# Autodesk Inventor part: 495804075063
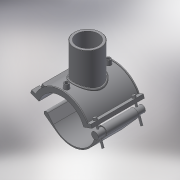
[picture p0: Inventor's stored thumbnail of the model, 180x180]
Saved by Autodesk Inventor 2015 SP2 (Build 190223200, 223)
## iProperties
Created: 2017-07
Part Number: 495804075063
Material: Generic
Description: PLASSON BRANCH SADDLE 75-63
Document SubType Name: Modeling
Designer: KIM
Density: 1 g/cm^3
Appearance: Default
Author: KIM
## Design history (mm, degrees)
derived "495804.ipt"
feature "Solid1::495804.ipt"
feature "Solid2::495804.ipt"
tag "TaggingFeature1"
body "Solid1"
body "Solid2"
other parameters: "d0" = 75, "d2" = 117, "d3" = 18.75, "d4" = 118, "d5" = 0, "d6" = 0.1, "d8" = 0, "d19" = 6, "d20" = 6, "d21" = 70.8, "d23" = 0, "d24" = 35.4, "d26" = 0, "d27" = 3, "d28" = 3, "d29" = 3, "d30" = 25, "d31" = 6, "d32" = 0, "d33" = 0, "d34" = 0.6, "d40" = 48.36, "d41" = 69.3, "d43" = 0, "d45" = 0, "d47" = 140.5, "d48" = 63, "d50" = 0, "d70" = 15, "d72" = 0, "d73" = 6, "d75" = 5, "d76" = 0, "d77" = 3.75, "d78" = 67.5, "d79" = 15, "d80" = 47.2, "d82" = 5 deg, "d84" = 4, "d85" = 14, "d86" = 0, "d87" = 3, "d88" = 0, "d89" = 1, "d90" = 1, "d91" = 94.4, "d92" = 0, "d93" = 0.5, "d94" = 39.47368, "d96" = 94.86, "d97" = 2.36, "d98" = 0, "d102" = 1.89, "d103" = 50.4, "d105" = 0, "d109" = -31.33333, "d117" = 0.63, "d120" = 140 deg, "d121" = 24.228, "d122" = 20 deg, "d123" = 186, "d124" = 55.8, "d126" = 0, "d143" = 78.75, "d150" = 13.5, "d159" = 3.6, "d161" = 1.875, "d162" = 70.8, "d163" = 0, "d167" = 15, "d168" = 42.27273, "d173" = 1, "d175" = 37.5, "d176" = 20 deg, "d177" = 5.25, "d178" = 18, "d180" = 0, "d185" = 38.35, "d186" = 38.35, "d187" = 46.5, "d188" = 5.4, "d189" = 5.25, "d190" = 0, "d191" = 69.75, "d200" = 9, "d202" = 0, "d216" = 106.2, "d217" = 0, "d221" = 43.66, "d222" = 5.25, "d223" = 3.15, "d224" = 37.5, "d225" = 3.15, "d227" = 10.8, "d230" = 46.5, "d236" = 20 deg, "d237" = 53.5, "d238" = 20 deg, "d239" = 5.25, "d_" = 75, "B_" = 117, "H_" = 94, "L_" = 118, "d_t" = 6, "d_1" = 63, "H_1" = 85, "d1" = 93, "d148" = 1.875, "d160" = 1.875
